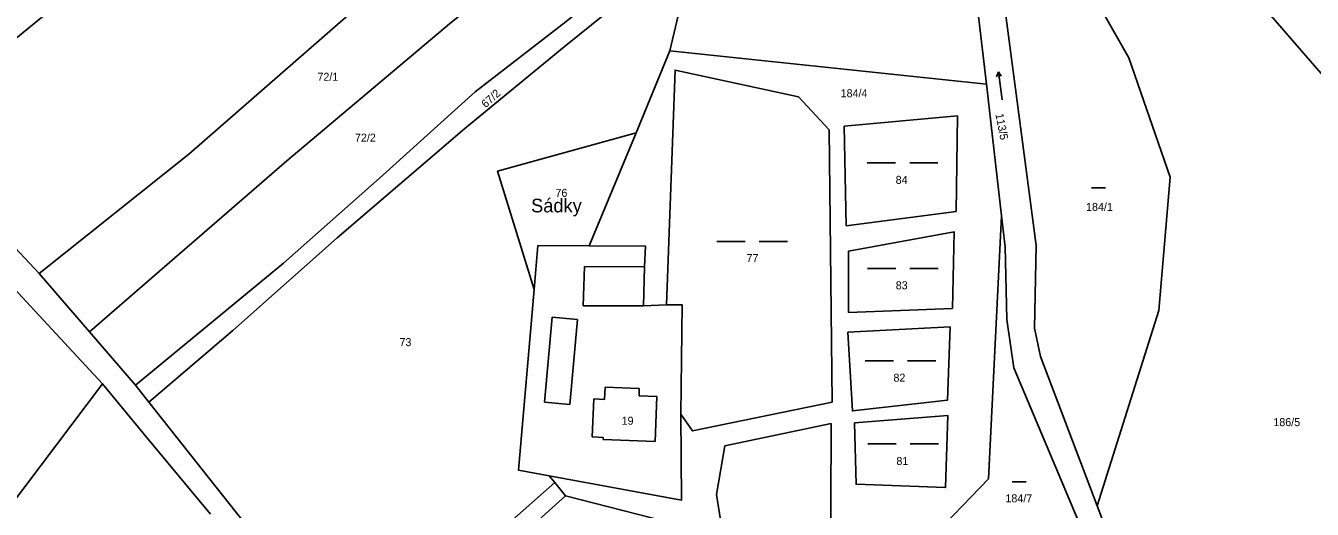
# Model space of a CAD drawing. Extents: x -7483133 to -743907, y -11317770 to -1129777.
# Drawn here: x -747509.1 to -747235.8, y -1131481.3 to -1131378.7 of the extents above; entities that cross this region are included whole.
import ezdxf

# ---------------------------------------------------------------- set-up
doc = ezdxf.new("R2010")
doc.units = 0
for name, color, linetype in [('Hranice parcel', 7, 'Continuous'), ('Parcelní čísla', 7, 'Continuous'), ('Pop  PČ popisy', 7, 'Continuous'), ('Vnitřní kresba', 7, 'Continuous'), ('Značky kultur', 7, 'Continuous')]:
    doc.layers.add(name, color=color, linetype=linetype)

msp = doc.modelspace()

# ---------------------------------------------------------------- linework, layer by layer
at = {"layer": 'Hranice parcel'}
for p, q in [((-747233.02, -1131389.89), (-747244.62, -1131376.47)), ((-747305.04, -1131391.08), (-747372.26, -1131384.03)), ((-747305.04, -1131391.08), (-747301.81, -1131418.99)), ((-747379.46, -1131401.41), (-747389.4, -1131425.41)), ((-747515.93, -1131429.75), (-747492.83, -1131454.72)), ((-747495.56, -1131443.68), (-747506.23, -1131431.25)), ((-747485.81, -1131454.98), (-747495.56, -1131443.68)), ((-747482.98, -1131458.6), (-747485.81, -1131454.98)), ((-747440.78, -1131511.65), (-747482.98, -1131458.6)), ((-747397.93, -1131474.19), (-747396.72, -1131475.66)), ((-747396.72, -1131475.66), (-747394.42, -1131478.45))]:
    msp.add_line(p, q, dxfattribs=at)
for points in [[(-747534.26, -1131400.17), (-747480.38, -1131356.14), (-747430.3, -1131312.29), (-747401.97, -1131292.55)], [(-747281.5, -1131480.62), (-747293.52, -1131448.9), (-747294.79, -1131442.89), (-747294.49, -1131425.32), (-747301.04, -1131375.44), (-747322.63, -1131321.35), (-747328.48, -1131310.88)], [(-747281.5, -1131480.62), (-747268.38, -1131439.1), (-747266.03, -1131410.81), (-747274.76, -1131385.48), (-747283.22, -1131370.63), (-747296.93, -1131350.55), (-747328.48, -1131310.88)], [(-747333.76, -1131315.41), (-747328.97, -1131323.74), (-747306.78, -1131376.04), (-747305.04, -1131391.08)], [(-747506.23, -1131431.25), (-747474.44, -1131405.95), (-747416.83, -1131355.62), (-747384.78, -1131331.55)], [(-747495.56, -1131443.68), (-747453.65, -1131407.36), (-747419.12, -1131378.23), (-747377.13, -1131344.4)], [(-747370.27, -1131355.92), (-747376.75, -1131363.63), (-747394.3, -1131377.78), (-747413.65, -1131392.68), (-747433.29, -1131410.44), (-747454.33, -1131429.09), (-747485.81, -1131454.98)], [(-747482.98, -1131458.6), (-747465.09, -1131443.35), (-747442.92, -1131423.66), (-747415.85, -1131400.46), (-747394.73, -1131383.14), (-747385.99, -1131376.16), (-747376.46, -1131367.68)], [(-747376.46, -1131367.68), (-747376.16, -1131373.4), (-747368.11, -1131366.26), (-747372.26, -1131384.03)], [(-747372.26, -1131384.03), (-747375.37, -1131391.54), (-747379.46, -1131401.41)], [(-747369.97, -1131461.1), (-747367.48, -1131464.7), (-747337.82, -1131458.55), (-747338.47, -1131400.78), (-747344.92, -1131393.73), (-747371.16, -1131388.1), (-747372.98, -1131437.9)], [(-747335.22, -1131400.02), (-747334.8, -1131421.12), (-747311.47, -1131418.08), (-747311.16, -1131397.83), (-747335.22, -1131400.02)], [(-747506.23, -1131431.25), (-747527.79, -1131408.31), (-747534.26, -1131400.17)], [(-747401.11, -1131434.68), (-747408.87, -1131409.55), (-747379.46, -1131401.41)], [(-747317.55, -1131488.29), (-747304.61, -1131474.88), (-747301.81, -1131418.99)], [(-747301.81, -1131418.99), (-747301.05, -1131425.58), (-747300.72, -1131441.01), (-747299.21, -1131451.29), (-747283.83, -1131487.76)], [(-747312.21, -1131438.68), (-747311.88, -1131422.44), (-747334.36, -1131426.55), (-747334.33, -1131439.56), (-747312.21, -1131438.68)], [(-747389.4, -1131425.41), (-747400.3, -1131425.35), (-747401.11, -1131434.68)], [(-747372.98, -1131437.9), (-747377.89, -1131438.1), (-747377.67, -1131429.84), (-747377.46, -1131425.43), (-747389.4, -1131425.41)], [(-747401.11, -1131434.68), (-747404.45, -1131472.99), (-747397.93, -1131474.19)], [(-747369.97, -1131461.1), (-747369.63, -1131437.93), (-747372.98, -1131437.9)], [(-747312.75, -1131442.56), (-747334.47, -1131443.75), (-747333.51, -1131460.43), (-747313.27, -1131458.14), (-747312.75, -1131442.56)], [(-747559.72, -1131546.32), (-747549.84, -1131533.09), (-747519.12, -1131489.53), (-747492.83, -1131454.72)], [(-747492.83, -1131454.72), (-747484.18, -1131465.15), (-747469.89, -1131482.38)], [(-747397.93, -1131474.19), (-747369.8, -1131479.36), (-747369.97, -1131461.1)], [(-747333.07, -1131463), (-747332.73, -1131476.01), (-747313.72, -1131476.71), (-747313.23, -1131461.4), (-747333.07, -1131463)], [(-747338.01, -1131463.14), (-747360.58, -1131467.85), (-747362.36, -1131478.2), (-747358.4, -1131503.3), (-747338.16, -1131498.03), (-747338.01, -1131463.14)], [(-747396.72, -1131475.66), (-747426.02, -1131501.54), (-747435.05, -1131510.7), (-747440.78, -1131511.65)], [(-747394.42, -1131478.45), (-747419.83, -1131501.28), (-747436.17, -1131516.88)], [(-747361.9, -1131590.13), (-747365.35, -1131560.17), (-747372.37, -1131506.82), (-747366.74, -1131485.54), (-747394.42, -1131478.45)], [(-747283.83, -1131487.76), (-747282.33, -1131491.3), (-747278.5, -1131492.8), (-747278.1, -1131489.61), (-747281.5, -1131480.62)]]:
    msp.add_lwpolyline(points, dxfattribs=at)
at = {"layer": 'Vnitřní kresba'}
for p, q in [((-747390.39, -1131429.79), (-747390.69, -1131438.14)), ((-747377.67, -1131429.84), (-747390.39, -1131429.79)), ((-747377.89, -1131438.1), (-747390.69, -1131438.14)), ((-747398.89, -1131458.55), (-747397.26, -1131440.57)), ((-747397.26, -1131440.57), (-747391.9, -1131441.06)), ((-747391.9, -1131441.06), (-747393.5, -1131459.05)), ((-747386.16, -1131457.98), (-747386.04, -1131455.42)), ((-747378.77, -1131455.66), (-747386.04, -1131455.42)), ((-747378.83, -1131457.21), (-747378.77, -1131455.66)), ((-747393.5, -1131459.05), (-747398.89, -1131458.55)), ((-747388.79, -1131465.97), (-747388.46, -1131457.89)), ((-747388.46, -1131457.89), (-747386.16, -1131457.98)), ((-747375.02, -1131457.35), (-747378.83, -1131457.21)), ((-747375.38, -1131466.95), (-747375.02, -1131457.35)), ((-747386.47, -1131466.05), (-747388.79, -1131465.97)), ((-747386.47, -1131466.53), (-747386.47, -1131466.05)), ((-747375.38, -1131466.95), (-747386.47, -1131466.53))]:
    msp.add_line(p, q, dxfattribs=at)
at = {"layer": 'Značky kultur'}
for p, q in [((-747302.5, -1131388.45), (-747302.86, -1131389.49)), ((-747301.67, -1131394.39), (-747302.5, -1131388.45)), ((-747302.5, -1131388.45), (-747301.87, -1131389.35)), ((-747330.33, -1131407.75), (-747324.33, -1131407.75)), ((-747321.33, -1131407.75), (-747315.33, -1131407.75)), ((-747282.72, -1131413.08), (-747279.72, -1131413.08)), ((-747362.3, -1131424.48), (-747356.3, -1131424.48)), ((-747353.3, -1131424.48), (-747347.3, -1131424.48)), ((-747330.3, -1131430.24), (-747324.3, -1131430.24)), ((-747321.3, -1131430.24), (-747315.3, -1131430.24)), ((-747330.77, -1131449.83), (-747324.77, -1131449.83)), ((-747321.77, -1131449.83), (-747315.77, -1131449.83)), ((-747330.24, -1131467.42), (-747324.24, -1131467.42)), ((-747321.24, -1131467.42), (-747315.24, -1131467.42)), ((-747299.58, -1131475.47), (-747296.58, -1131475.47))]:
    msp.add_line(p, q, dxfattribs=at)

# ---------------------------------------------------------------- texts
at = {"layer": 'Parcelní čísla'}
for s, p in [('72/1', (-747447.14, -1131390.36)), ('184/4', (-747336, -1131393.85)), ('72/2', (-747439.17, -1131403.28)), ('84', (-747324.31, -1131412.24)), ('76', (-747396.58, -1131415)), ('184/1', (-747283.87, -1131417.98)), ('77', (-747356, -1131428.85)), ('83', (-747324.3, -1131434.63)), ('73', (-747429.71, -1131446.69)), ('82', (-747324.78, -1131454.23)), ('19', (-747382.52, -1131463.37)), ('186/5', (-747244.08, -1131463.67)), ('81', (-747324.15, -1131471.92)), ('184/7', (-747301, -1131479.85))]:
    msp.add_text(s, height=1.7, dxfattribs=at).set_placement(p)
for s, rotation, p in [('67/2', 42, (-747411.4, -1131396.21)), ('113/5', 281, (-747303.13, -1131397.44))]:
    msp.add_text(s, height=1.7, rotation=rotation, dxfattribs=at).set_placement(p)
at = {"layer": 'Pop  PČ popisy'}
msp.add_text('Sádky', height=2.9, dxfattribs=at).set_placement((-747401.76, -1131418.29))

doc.saveas('drawing.dxf')
